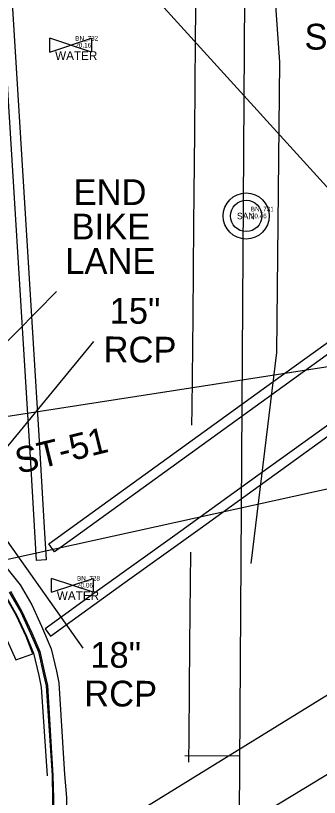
# Model space of a CAD drawing. Extents: x 509744 to 512285, y 1314862 to 1316822.
# Drawn here: x 510461.1 to 510494.1, y 1315900.5 to 1315985.3 of the extents above; entities that cross this region are included whole.
import ezdxf

# ---------------------------------------------------------------- set-up
doc = ezdxf.new("R2010")
doc.units = 0
for name, color, linetype in [('BaselineSurvey', 7, 'Continuous'), ('CGBack_ep', 7, 'Continuous'), ('CGep_ep', 7, 'Continuous'), ('CGFace_ep', 7, 'Continuous'), ('CurbRampWarning_ep', 7, 'Continuous'), ('ElecAer_ep', 7, 'Continuous'), ('ManholeSS_ep', 7, 'Continuous'), ('NonPlottingEle_dp', 7, 'Continuous'), ('PavtAsphalt_ep', 7, 'Continuous'), ('PavtAsphaltCrown_ep', 7, 'Continuous'), ('PavtBreak_ep', 7, 'Continuous'), ('PMRK_ep', 7, 'Continuous'), ('RailroadXing_ep', 7, 'Continuous'), ('TextElevLabel', 7, 'Continuous'), ('TextPtLabel', 7, 'Continuous'), ('TextTopoLabel_ep', 7, 'Continuous'), ('ValveWater_ep', 7, 'Continuous')]:
    doc.layers.add(name, color=color, linetype=linetype)

msp = doc.modelspace()

# ---------------------------------------------------------------- linework, layer by layer
at = {"layer": 'BaselineSurvey'}
for p, q in [((510484.134, 1315694.907), (510491.264, 1316815.908)), ((510485.47, 1315904.926), (510479.47, 1315904.964))]:
    msp.add_line(p, q, dxfattribs=at)
at = {"layer": 'CGBack_ep'}
msp.add_lwpolyline([(510459.985, 1315922.45), (510461.227, 1315920.273), (510462.296, 1315917.956), (510463.071, 1315916.113), (510463.634, 1315913.677), (510463.9, 1315912.426), (510464.537, 1315902.784)], dxfattribs=at)
at = {"layer": 'CGep_ep'}
msp.add_lwpolyline([(510460.548, 1315922.827), (510461.79, 1315920.65), (510462.859, 1315918.334), (510463.728, 1315916.277), (510464.291, 1315913.842), (510464.558, 1315912.591), (510465.152, 1315902.835), (510465.225, 1315900.335), (510465.247, 1315897.83), (510465.299, 1315897.273)], dxfattribs=at)
at = {"layer": 'CGFace_ep'}
msp.add_lwpolyline([(510460.425, 1315922.745), (510461.667, 1315920.568), (510462.736, 1315918.251), (510463.585, 1315916.241), (510464.148, 1315913.806), (510464.414, 1315912.555), (510465.07, 1315902.828), (510465.124, 1315900.326), (510465.146, 1315897.822), (510465.191, 1315897.26)], dxfattribs=at)
at = {"layer": 'CurbRampWarning_ep'}
msp.add_lwpolyline([(510458.571, 1315921.024), (510461.121, 1315915.38), (510462.986, 1315916.049), (510462.268, 1315917.937), (510461.17, 1315920.249), (510457.981, 1315925.75), (510458.571, 1315921.024)], dxfattribs=at)
at = {"layer": 'ElecAer_ep'}
for points in [[(510447.916, 1315923.604), (510519.717, 1315939.401), (510434.348, 1316033.385), (510447.882, 1315923.851)], [(510525.108, 1315951.865), (510419.206, 1315935.43), (510273.562, 1315935.372), (510178.5, 1315925.306)]]:
    msp.add_lwpolyline(points, dxfattribs=at)
at = {"layer": 'ManholeSS_ep'}
for radius in [2.5, 1.7]:
    msp.add_circle((510486.145, 1315963.577), radius, dxfattribs=at)
at = {"layer": 'NonPlottingEle_dp'}
for p, q in [((510454.186, 1315931.214), (510469.622, 1315949.938)), ((510458.127, 1315931.159), (510468.417, 1315916.642))]:
    msp.add_line(p, q, dxfattribs=at)
at = {"layer": 'PavtAsphalt_ep'}
msp.add_line((510458.517, 1315927.345), (510461.616, 1315923.543), dxfattribs=at)
msp.add_lwpolyline([(510461.616, 1315923.543), (510462.858, 1315921.366), (510463.927, 1315919.049), (510464.976, 1315916.59), (510465.539, 1315914.155), (510465.805, 1315912.904), (510466.434, 1315902.941), (510466.64, 1315900.451), (510466.662, 1315897.947), (510466.673, 1315897.737)], dxfattribs=at)
at = {"layer": 'PavtAsphaltCrown_ep'}
for points in [[(510487.857, 1316252.334), (510487.145, 1316228.217), (510487.802, 1316209.666), (510487.298, 1316196.938), (510487.463, 1316175.759), (510486.8, 1316155.464), (510487.041, 1316127.532), (510486.794, 1316112.305), (510487.178, 1316086.167), (510486.773, 1316064.916), (510486.628, 1316038.076), (510487.142, 1316017.171), (510489.752, 1315980.275)], [(510489.752, 1315980.275), (510489.426, 1315948.771), (510486.649, 1315925.835)]]:
    msp.add_lwpolyline(points, dxfattribs=at)
at = {"layer": 'PavtBreak_ep'}
for points in [[(510481.48, 1316072.655), (510481.384, 1316062.656), (510481.289, 1316052.656), (510481.194, 1316042.656), (510481.098, 1316032.657), (510481.003, 1316022.657), (510480.908, 1316012.658), (510480.812, 1316002.658), (510480.717, 1315992.659), (510480.622, 1315982.659), (510480.526, 1315972.66), (510480.431, 1315962.66), (510480.336, 1315952.661), (510480.24, 1315942.661), (510480.223, 1315940.852)], [(510480.092, 1315927.095), (510479.997, 1315917.096), (510479.901, 1315907.096), (510479.874, 1315904.262)]]:
    msp.add_lwpolyline(points, dxfattribs=at)
at = {"layer": 'PMRK_ep'}
for points in [[(510460.575, 1315989.648), (510461.183, 1315979.666), (510461.792, 1315969.685), (510462.4, 1315959.703), (510463.008, 1315949.722), (510463.616, 1315939.74), (510464.225, 1315929.759), (510464.439, 1315926.245), (510463.393, 1315926.182), (510462.785, 1315936.163), (510462.177, 1315946.145), (510461.568, 1315956.126), (510460.96, 1315966.108), (510460.352, 1315976.089), (510459.744, 1315986.071)], [(510464.722, 1315927.965), (510472.824, 1315933.827), (510480.925, 1315939.69), (510489.027, 1315945.552), (510497.128, 1315951.414), (510505.23, 1315957.276), (510513.331, 1315963.138), (510515.507, 1315964.712), (510516.125, 1315963.857), (510508.024, 1315957.995), (510499.922, 1315952.133), (510491.821, 1315946.271), (510483.719, 1315940.409), (510475.618, 1315934.547), (510467.516, 1315928.684), (510465.341, 1315927.11), (510464.722, 1315927.965)], [(510510.829, 1315952.281), (510502.717, 1315946.434), (510494.604, 1315940.586), (510486.492, 1315934.739), (510478.38, 1315928.892), (510470.268, 1315923.044), (510464.332, 1315918.766), (510464.909, 1315917.966), (510473.021, 1315923.813), (510481.134, 1315929.66), (510489.246, 1315935.508), (510497.358, 1315941.355), (510505.471, 1315947.202), (510511.406, 1315951.481), (510510.829, 1315952.281)]]:
    msp.add_lwpolyline(points, dxfattribs=at)
at = {"layer": 'RailroadXing_ep'}
msp.add_lwpolyline([(510510.582, 1315921.202), (510512.01, 1315919.228), (510509.816, 1315917.634), (510511.971, 1315913.247), (510456.241, 1315879.479), (510455.173, 1315881.471), (510457.955, 1315883.273), (510455.55, 1315887.297)], close=True, dxfattribs=at)
at = {"layer": 'TextTopoLabel_ep'}
msp.add_line((510442.28, 1315931.732), (510465.537, 1315955.388), dxfattribs=at)
at = {"layer": 'ValveWater_ep'}
for p, q in [((510469.338, 1315981.367), (510464.838, 1315982.867)), ((510464.838, 1315981.367), (510469.338, 1315982.867)), ((510464.838, 1315981.367), (510464.838, 1315982.867)), ((510469.338, 1315982.867), (510469.338, 1315981.367)), ((510469.526, 1315922.736), (510465.026, 1315924.236)), ((510465.026, 1315922.736), (510469.526, 1315924.236)), ((510465.026, 1315922.736), (510465.026, 1315924.236)), ((510469.526, 1315924.236), (510469.526, 1315922.736))]:
    msp.add_line(p, q, dxfattribs=at)

# ---------------------------------------------------------------- texts
at = {"layer": 'ManholeSS_ep'}
msp.add_text('SAN', height=0.7, dxfattribs=at).set_placement((510485.136, 1315963.227))
at = {"layer": 'NonPlottingEle_dp'}
msp.add_text('ST-56', height=2.8, dxfattribs=at).set_placement((510492.474, 1315981.642))
for s, rotation, p in [('15"', 359.66722, (510471.317, 1315951.894)), ('RCP', 359.66722, (510470.656, 1315947.698)), ('ST-51', 13.81088, (510461.447, 1315935.557)), ('18"', 359.66722, (510469.217, 1315914.542)), ('RCP', 359.66722, (510468.556, 1315910.346))]:
    msp.add_text(s, height=2.8, rotation=rotation, dxfattribs=at).set_placement(p)
at = {"layer": 'TextElevLabel'}
for s, p in [('20.16', (510467.588, 1315981.867)), ('20.46', (510486.645, 1315963.327)), ('20.06', (510467.776, 1315923.236))]:
    msp.add_text(s, height=0.5, dxfattribs=at).set_placement(p)
at = {"layer": 'TextPtLabel'}
for s, p in [('BN_732', (510467.588, 1315982.617)), ('BN_731', (510486.645, 1315964.077)), ('BN_728', (510467.776, 1315923.986))]:
    msp.add_text(s, height=0.5, dxfattribs=at).set_placement(p)
at = {"layer": 'TextTopoLabel_ep'}
for s, p in [('END', (510467.413, 1315964.77)), ('BIKE', (510467.191, 1315961.031)), ('LANE', (510466.503, 1315957.292))]:
    msp.add_text(s, height=2.8, dxfattribs=at).set_placement(p)
at = {"layer": 'ValveWater_ep'}
for p in [(510465.399, 1315980.517), (510465.587, 1315921.886)]:
    msp.add_text('WATER', height=0.95, dxfattribs=at).set_placement(p)

doc.saveas('drawing.dxf')
